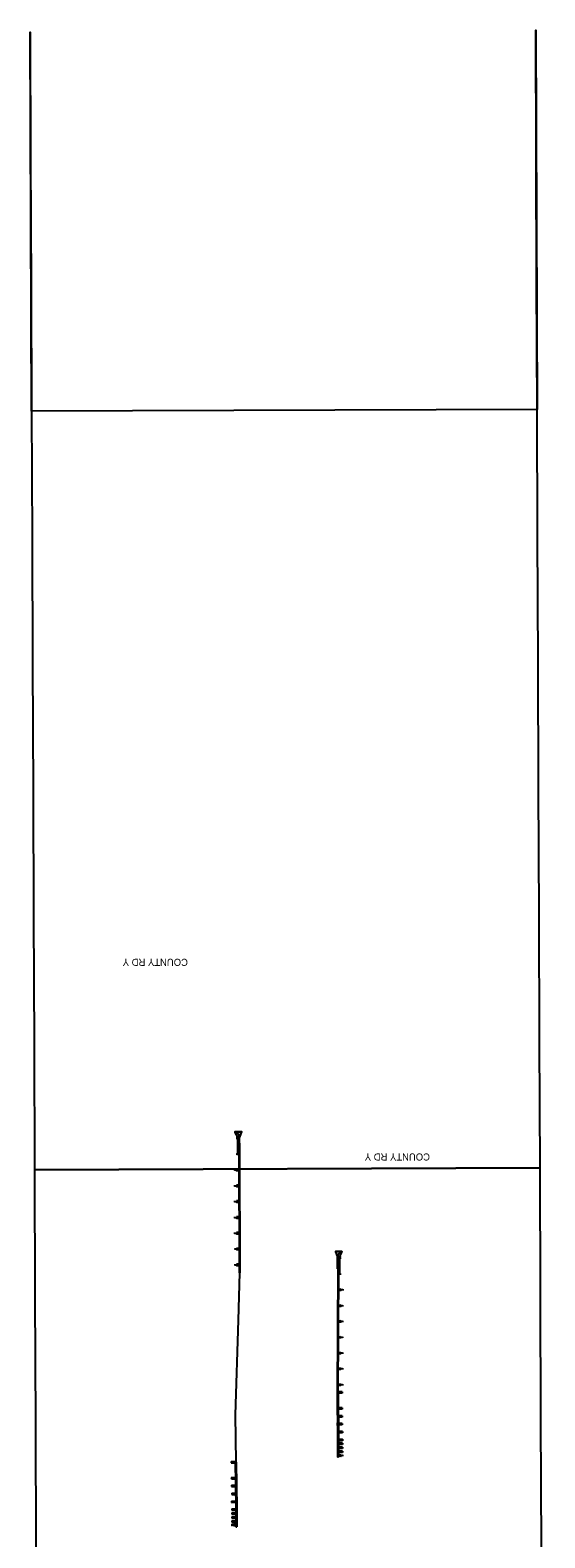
# Model space of a CAD drawing. Extents: x 181105 to 189133, y 406929 to 500404.
# Drawn here: x 181643 to 181846, y 415783 to 416380 of the extents above; entities that cross this region are included whole.
import ezdxf

# ---------------------------------------------------------------- set-up
doc = ezdxf.new("R2010")
doc.units = 0
for name, color, linetype in [('SH_Named_Boundary', 7, 'Continuous'), ('SH_Text', 7, 'Continuous'), ('UT_X_Electric_Cells', 7, 'Continuous'), ('UT_X_Telecom_Cells', 7, 'Continuous')]:
    doc.layers.add(name, color=color, linetype=linetype)

msp = doc.modelspace()

# ---------------------------------------------------------------- linework, layer by layer
at = {"layer": 'SH_Named_Boundary'}
for points in [[(181644.38, 415929.12), (181844.38, 415929.88), (181844.19, 415979.88), (181844, 416029.88), (181843.81, 416079.88), (181843.62, 416129.88), (181843.42, 416179.88), (181843.23, 416229.88), (181843.04, 416279.88), (181842.85, 416329.88), (181842.66, 416379.88), (181843.23, 416229.88), (181643.23, 416229.11), (181642.66, 416379.11), (181642.85, 416329.11), (181643.04, 416279.11), (181643.23, 416229.11), (181643.43, 416179.11), (181643.62, 416129.11), (181643.81, 416079.11), (181644, 416029.11), (181644.19, 415979.12)], [(181646.29, 415429.12), (181846.29, 415429.88), (181846.1, 415479.88), (181845.91, 415529.88), (181845.72, 415579.88), (181845.53, 415629.88), (181845.33, 415679.88), (181845.14, 415729.88), (181844.95, 415779.88), (181844.76, 415829.88), (181844.57, 415879.88), (181844.38, 415929.88), (181644.38, 415929.12), (181644.57, 415879.12), (181644.76, 415829.12), (181644.95, 415779.12), (181645.15, 415729.12), (181645.34, 415679.12), (181645.53, 415629.12), (181645.72, 415579.12), (181645.91, 415529.12), (181646.1, 415479.12)]]:
    msp.add_lwpolyline(points, close=True, dxfattribs=at)
at = {"layer": 'UT_X_Electric_Cells'}
for p, q in [((181724.41, 415941.75), (181724.42, 415941.25)), ((181725.16, 415941.75), (181725.17, 415941.25)), ((181724.41, 415941.5), (181725.16, 415941.5)), ((181724.42, 415941.25), (181725.17, 415941.25)), ((181724.6, 415941.25), (181724.73, 415941.13)), ((181724.73, 415941.25), (181724.75, 415935.5)), ((181724.85, 415941.25), (181724.88, 415935.5)), ((181724.98, 415941.25), (181724.85, 415941.13)), ((181725.06, 415937.33), (181725.17, 415941.25)), ((181725.06, 415937.33), (181725.56, 415937.34)), ((181725.18, 415937.34), (181725.37, 415888.38)), ((181725.43, 415937.34), (181725.62, 415888.38)), ((181724.44, 415935.5), (181724.44, 415935)), ((181724.44, 415935.5), (181725.19, 415935.5)), ((181724.44, 415935.25), (181725.19, 415935.25)), ((181724.63, 415935.5), (181724.75, 415935.63)), ((181725, 415935.5), (181724.87, 415935.63)), ((181725.19, 415935.5), (181725.19, 415935)), ((181723.46, 415929.25), (181723.46, 415928.75)), ((181723.46, 415929), (181724.21, 415929)), ((181724.21, 415929.25), (181724.21, 415928.75)), ((181724.21, 415929.25), (181725.21, 415928.75)), ((181724.21, 415928.75), (181725.21, 415929.25)), ((181725.46, 415929), (181725.46, 415929)), ((181723.49, 415923), (181723.49, 415922.5)), ((181723.49, 415922.75), (181724.24, 415922.75)), ((181724.24, 415923), (181724.24, 415922.5)), ((181724.24, 415923), (181725.24, 415922.5)), ((181724.24, 415922.5), (181725.24, 415923)), ((181723.51, 415916.75), (181723.51, 415916.25)), ((181723.51, 415916.5), (181724.26, 415916.5)), ((181724.26, 415916.75), (181724.26, 415916.25)), ((181724.26, 415916.75), (181725.26, 415916.25)), ((181724.26, 415916.25), (181725.26, 415916.75)), ((181723.53, 415910.5), (181723.54, 415910)), ((181723.53, 415910.25), (181724.28, 415910.25)), ((181724.28, 415910.5), (181724.29, 415910)), ((181724.28, 415910.5), (181725.29, 415910)), ((181724.29, 415910), (181725.28, 415910.5)), ((181723.56, 415904.25), (181723.56, 415903.75)), ((181723.56, 415904), (181724.31, 415904)), ((181724.31, 415904.25), (181724.31, 415903.75)), ((181724.31, 415904.25), (181725.31, 415903.75)), ((181724.31, 415903.75), (181725.31, 415904.25)), ((181723.58, 415898), (181723.58, 415897.5)), ((181723.58, 415897.75), (181724.33, 415897.75)), ((181724.33, 415898), (181724.33, 415897.5)), ((181724.33, 415898), (181725.33, 415897.5)), ((181724.33, 415897.5), (181725.33, 415898)), ((181764.62, 415894.29), (181764.62, 415893.79)), ((181765.37, 415894.04), (181764.62, 415894.04)), ((181765.37, 415894.29), (181765.37, 415893.79)), ((181723.61, 415891.75), (181723.61, 415891.25)), ((181723.61, 415891.5), (181724.36, 415891.5)), ((181724.36, 415891.75), (181724.36, 415891.25)), ((181724.36, 415891.75), (181725.36, 415891.25)), ((181724.36, 415891.25), (181725.36, 415891.75)), ((181725.37, 415888.38), (181725.62, 415888.38)), ((181764.35, 415889.88), (181764.17, 415840.92)), ((181764.73, 415889.88), (181764.23, 415889.88)), ((181764.6, 415889.88), (181764.42, 415840.92)), ((181765.37, 415893.79), (181764.62, 415893.79)), ((181764.73, 415889.88), (181764.62, 415893.79)), ((181764.78, 415888.04), (181764.91, 415888.17)), ((181764.81, 415893.79), (181764.93, 415893.67)), ((181764.93, 415893.79), (181764.91, 415888.04)), ((181765.06, 415893.79), (181765.03, 415888.04)), ((181765.16, 415888.04), (181765.04, 415888.17)), ((181765.18, 415893.79), (181765.06, 415893.67)), ((181764.6, 415888.04), (181764.6, 415887.54)), ((181765.35, 415888.04), (181764.6, 415888.04)), ((181765.35, 415887.79), (181764.6, 415887.79)), ((181765.35, 415888.04), (181765.35, 415887.54)), ((181764.32, 415881.54), (181764.32, 415881.54)), ((181765.57, 415881.79), (181764.57, 415881.29)), ((181765.57, 415881.29), (181764.57, 415881.79)), ((181765.57, 415881.79), (181765.57, 415881.29)), ((181766.32, 415881.54), (181765.57, 415881.54)), ((181766.32, 415881.79), (181766.32, 415881.29)), ((181765.55, 415875.54), (181764.55, 415875.04)), ((181765.55, 415875.04), (181764.55, 415875.54)), ((181765.55, 415875.54), (181765.55, 415875.04)), ((181766.3, 415875.29), (181765.55, 415875.29)), ((181766.3, 415875.54), (181766.3, 415875.04)), ((181765.53, 415869.29), (181764.52, 415868.79)), ((181765.52, 415868.79), (181764.53, 415869.29)), ((181765.53, 415869.29), (181765.52, 415868.79)), ((181766.27, 415869.04), (181765.52, 415869.04)), ((181766.28, 415869.29), (181766.27, 415868.79)), ((181765.5, 415863.04), (181764.5, 415862.54)), ((181765.5, 415862.54), (181764.5, 415863.04)), ((181765.5, 415863.04), (181765.5, 415862.54)), ((181766.25, 415862.79), (181765.5, 415862.79)), ((181766.25, 415863.04), (181766.25, 415862.54)), ((181765.48, 415856.79), (181764.48, 415856.29)), ((181765.48, 415856.29), (181764.48, 415856.79)), ((181765.48, 415856.79), (181765.48, 415856.29)), ((181766.23, 415856.54), (181765.48, 415856.54)), ((181766.23, 415856.79), (181766.23, 415856.29)), ((181765.45, 415850.54), (181764.45, 415850.04)), ((181765.45, 415850.04), (181764.45, 415850.54)), ((181765.45, 415850.54), (181765.45, 415850.04)), ((181766.2, 415850.29), (181765.45, 415850.29)), ((181766.2, 415850.54), (181766.2, 415850.04)), ((181764.17, 415840.92), (181764.24, 415822.73)), ((181764.42, 415840.92), (181764.17, 415840.92)), ((181765.43, 415844.29), (181764.43, 415843.79)), ((181765.43, 415843.79), (181764.43, 415844.29)), ((181764.55, 415841.46), (181764.62, 415822.73)), ((181766.06, 415841.2), (181764.55, 415841.19)), ((181766.06, 415840.66), (181764.55, 415840.65)), ((181765.31, 415841.2), (181765.31, 415840.66)), ((181765.43, 415844.29), (181765.43, 415843.79)), ((181766.18, 415844.04), (181765.43, 415844.04)), ((181766.06, 415841.2), (181766.06, 415840.66)), ((181766.18, 415844.29), (181766.18, 415843.79)), ((181766.14, 415834.92), (181764.57, 415834.92)), ((181766.15, 415834.38), (181764.57, 415834.38)), ((181765.4, 415834.92), (181765.4, 415834.38)), ((181766.14, 415834.92), (181766.15, 415834.38)), ((181764.22, 415828.96), (181764.49, 415828.96)), ((181764.22, 415827.87), (181764.22, 415828.96)), ((181764.6, 415828.96), (181764.49, 415828.96)), ((181766.11, 415831.81), (181764.58, 415831.8)), ((181766.11, 415831.27), (181764.59, 415831.26)), ((181766.12, 415828.72), (181764.6, 415828.71)), ((181765.36, 415831.81), (181765.36, 415831.27)), ((181765.38, 415828.72), (181765.38, 415828.17)), ((181766.11, 415831.81), (181766.11, 415831.27)), ((181766.12, 415828.72), (181766.13, 415828.18)), ((181764.24, 415822.73), (181764.27, 415815.4)), ((181766.13, 415828.18), (181764.6, 415828.17)), ((181766.22, 415825.59), (181764.61, 415825.58)), ((181766.22, 415825.05), (181764.61, 415825.04)), ((181764.62, 415822.73), (181764.65, 415815.41)), ((181766.2, 415822.46), (181764.62, 415822.45)), ((181765.46, 415822.45), (181765.46, 415821.91)), ((181765.47, 415825.59), (181765.48, 415825.05)), ((181766.2, 415822.46), (181766.21, 415821.92)), ((181766.22, 415825.59), (181766.22, 415825.05)), ((181764.34, 415816.49), (181764.65, 415816.5)), ((181764.34, 415816.49), (181764.34, 415815.41)), ((181766.21, 415821.92), (181764.63, 415821.91)), ((181766.21, 415820.91), (181764.63, 415820.91)), ((181766.21, 415820.37), (181764.63, 415820.37)), ((181766.24, 415819.35), (181764.64, 415819.35)), ((181766.24, 415818.81), (181764.64, 415818.81)), ((181766.25, 415817.79), (181764.64, 415817.79)), ((181766.25, 415817.25), (181764.64, 415817.25)), ((181765.46, 415820.91), (181765.47, 415820.37)), ((181765.49, 415819.35), (181765.49, 415818.81)), ((181765.51, 415817.79), (181765.51, 415817.25)), ((181766.21, 415820.91), (181766.21, 415820.37)), ((181766.24, 415819.35), (181766.24, 415818.81)), ((181766.25, 415817.79), (181766.25, 415817.25)), ((181722.22, 415813.66), (181723.73, 415813.68)), ((181722.22, 415813.66), (181722.23, 415813.12)), ((181722.23, 415813.12), (181723.74, 415813.14)), ((181722.97, 415813.67), (181722.97, 415813.13)), ((181723.73, 415813.95), (181724, 415795.22)), ((181724.11, 415813.42), (181724.38, 415795.23)), ((181764.27, 415815.92), (181764.27, 415815.92)), ((181764.65, 415815.41), (181764.27, 415815.4)), ((181764.65, 415816.37), (181765.62, 415816.37)), ((181765.62, 415815.83), (181764.65, 415815.83)), ((181765.61, 415816.37), (181765.67, 415816.37)), ((181765.61, 415815.83), (181765.68, 415815.83)), ((181765.63, 415816.37), (181765.63, 415815.83)), ((181765.63, 415815.83), (181765.68, 415815.83)), ((181765.67, 415816.37), (181765.67, 415816.17)), ((181765.68, 415816.03), (181765.68, 415815.83)), ((181765.72, 415816.12), (181766.15, 415816.12)), ((181765.73, 415816.07), (181766.14, 415816.08)), ((181766.18, 415816.03), (181766.19, 415815.83)), ((181766.19, 415815.84), (181766.23, 415815.84)), ((181766.2, 415816.38), (181766.2, 415816.17)), ((181766.2, 415816.38), (181766.23, 415816.38)), ((181766.23, 415816.38), (181766.23, 415815.84)), ((181722.25, 415807.39), (181723.82, 415807.41)), ((181722.25, 415807.39), (181722.26, 415806.85)), ((181722.26, 415806.85), (181723.83, 415806.87)), ((181722.99, 415807.4), (181723, 415806.86)), ((181722.35, 415804.27), (181723.87, 415804.3)), ((181722.35, 415804.27), (181722.35, 415803.73)), ((181722.35, 415803.73), (181723.87, 415803.76)), ((181722.39, 415801.18), (181723.91, 415801.2)), ((181722.39, 415801.18), (181722.39, 415800.64)), ((181722.39, 415800.64), (181723.92, 415800.66)), ((181723.09, 415804.28), (181723.1, 415803.74)), ((181723.13, 415801.19), (181723.14, 415800.65)), ((181723.91, 415801.46), (181724.01, 415801.46)), ((181724.29, 415801.46), (181724.01, 415801.46)), ((181724.3, 415800.37), (181724.29, 415801.46)), ((181722.35, 415798.05), (181723.96, 415798.08)), ((181722.35, 415798.05), (181722.35, 415797.51)), ((181722.35, 415797.51), (181723.96, 415797.54)), ((181722.42, 415794.92), (181724, 415794.94)), ((181722.42, 415794.92), (181722.43, 415794.38)), ((181722.43, 415794.38), (181724.01, 415794.4)), ((181722.44, 415793.38), (181724.02, 415793.4)), ((181722.44, 415793.38), (181722.45, 415792.84)), ((181722.45, 415792.84), (181724.03, 415792.86)), ((181723.09, 415798.07), (181723.1, 415797.52)), ((181723.17, 415794.93), (181723.17, 415794.39)), ((181723.19, 415793.39), (181723.2, 415792.85)), ((181724, 415795.22), (181724.1, 415787.9)), ((181724.38, 415795.23), (181724.48, 415787.9)), ((181722.45, 415791.82), (181724.05, 415791.84)), ((181722.45, 415791.82), (181722.45, 415791.28)), ((181722.45, 415791.28), (181724.05, 415791.3)), ((181722.46, 415790.26), (181724.07, 415790.28)), ((181722.46, 415790.26), (181722.47, 415789.72)), ((181722.47, 415789.72), (181724.08, 415789.74)), ((181722.5, 415788.84), (181722.51, 415788.3)), ((181722.54, 415788.84), (181722.5, 415788.84)), ((181722.56, 415788.3), (181722.51, 415788.3)), ((181722.54, 415788.84), (181722.54, 415788.64)), ((181722.56, 415788.5), (181722.56, 415788.3)), ((181723.02, 415788.6), (181722.59, 415788.59)), ((181723.01, 415788.55), (181722.61, 415788.54)), ((181723.12, 415788.85), (181723.06, 415788.84)), ((181723.06, 415788.84), (181723.07, 415788.64)), ((181723.06, 415788.5), (181723.07, 415788.3)), ((181723.13, 415788.31), (181723.07, 415788.3)), ((181723.11, 415788.31), (181723.07, 415788.3)), ((181723.11, 415788.85), (181723.11, 415788.31)), ((181724.09, 415788.86), (181723.12, 415788.85)), ((181723.13, 415788.31), (181724.1, 415788.32)), ((181723.19, 415791.83), (181723.2, 415791.29)), ((181723.2, 415790.27), (181723.21, 415789.73)), ((181724.4, 415788.99), (181724.09, 415788.99)), ((181724.1, 415787.9), (181724.48, 415787.9)), ((181724.4, 415788.99), (181724.41, 415787.91)), ((181724.48, 415788.42), (181724.48, 415788.42))]:
    msp.add_line(p, q, dxfattribs=at)
for points in [[(181726.28, 415944.13), (181725.54, 415942), (181724.79, 415942), (181723.78, 415943.87), (181723.78, 415944.25), (181726.28, 415944.26)], [(181725.16, 415942), (181725.16, 415942.17), (181724.41, 415942.17), (181724.41, 415942)], [(181724.21, 415929.25), (181724.21, 415928.75), (181725.21, 415928.75), (181725.21, 415929.25)], [(181724.24, 415923), (181724.24, 415922.5), (181725.24, 415922.5), (181725.24, 415923)], [(181724.26, 415916.75), (181724.26, 415916.25), (181725.26, 415916.25), (181725.26, 415916.75)], [(181724.28, 415910.5), (181724.29, 415910), (181725.29, 415910), (181725.28, 415910.5)], [(181724.31, 415904.25), (181724.31, 415903.75), (181725.31, 415903.75), (181725.31, 415904.25)], [(181724.33, 415898), (181724.33, 415897.5), (181725.33, 415897.5), (181725.33, 415898)], [(181763.51, 415896.67), (181764.25, 415894.55), (181765, 415894.54), (181766, 415896.41), (181766.01, 415896.79), (181763.51, 415896.8)], [(181764.62, 415894.54), (181764.62, 415894.71), (181765.37, 415894.71), (181765.37, 415894.54)], [(181724.36, 415891.75), (181724.36, 415891.25), (181725.36, 415891.25), (181725.36, 415891.75)], [(181765.57, 415881.79), (181765.57, 415881.29), (181764.57, 415881.29), (181764.57, 415881.79)], [(181765.55, 415875.54), (181765.55, 415875.04), (181764.55, 415875.04), (181764.55, 415875.54)], [(181765.53, 415869.29), (181765.52, 415868.79), (181764.52, 415868.79), (181764.53, 415869.29)], [(181765.5, 415863.04), (181765.5, 415862.54), (181764.5, 415862.54), (181764.5, 415863.04)], [(181765.48, 415856.79), (181765.48, 415856.29), (181764.48, 415856.29), (181764.48, 415856.79)], [(181765.45, 415850.54), (181765.45, 415850.04), (181764.45, 415850.04), (181764.45, 415850.54)], [(181765.43, 415844.29), (181765.43, 415843.79), (181764.43, 415843.79), (181764.43, 415844.29)]]:
    msp.add_lwpolyline(points, close=True, dxfattribs=at)
for points in [[(181723.78, 415944.25), (181723.78, 415944.12), (181726.28, 415944.13)], [(181725.56, 415937.34), (181725.54, 415942), (181725.16, 415942), (181725.17, 415941.25)], [(181766.01, 415896.79), (181766.01, 415896.66), (181763.51, 415896.67)], [(181764.23, 415889.88), (181764.25, 415894.55), (181764.62, 415894.54), (181764.62, 415893.79)]]:
    msp.add_lwpolyline(points, dxfattribs=at)
for centre, start, end in [((181723.66, 415942), 0.21749, 86.23856), ((181766.13, 415894.54), 93.76144, 179.78251)]:
    msp.add_arc(centre, 1.88, start, end, dxfattribs=at)
for centre, major_axis, start_param, end_param in [((181765.72, 415816.17), (0.0497, 0.0002), 3.141593, 4.712389), ((181765.73, 415816.03), (-0.0497, -0.0002), 4.712389, 6.283185), ((181766.14, 415816.03), (0.0497, 0.0002), 0, 1.570796), ((181766.15, 415816.17), (0.0497, 0.0002), 4.712389, 6.283185), ((181722.59, 415788.64), (-0.0497, -0.0007), 0, 1.570796), ((181722.61, 415788.5), (-0.0497, -0.0007), 4.712389, 6.283185), ((181723.02, 415788.5), (0.0497, 0.0007), 0, 1.570796), ((181723.02, 415788.64), (-0.0497, -0.0007), 1.570796, 3.141593)]:
    msp.add_ellipse(centre, major_axis=major_axis, ratio=0.906762, start_param=start_param, end_param=end_param, dxfattribs=at)
at = {"layer": 'UT_X_Telecom_Cells'}
msp.add_lwpolyline([(181724.11, 415813.42), (181723.85, 415832.08), (181725.11, 415869.59), (181725.62, 415888.38)], dxfattribs=at)

# ---------------------------------------------------------------- texts
at = {"layer": 'SH_Text'}
for p in [(181705.08, 416012.54), (181800.84, 415935.54)]:
    msp.add_text('COUNTY RD Y', height=2.8, rotation=180, dxfattribs=at).set_placement(p)

doc.saveas('drawing.dxf')
